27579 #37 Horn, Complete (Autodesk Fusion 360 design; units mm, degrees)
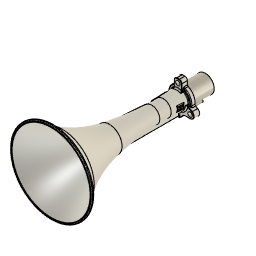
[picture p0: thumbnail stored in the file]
parameter "Bolt_Hole_Tolerance" = 1.5875 (= "( 1 / 16 ) * 1 in")
parameter "Dowel_Hole_Tolerance" = 0.0248 (= "( 1 / 1024 ) * 1 in")
canvas "Canvas1"
sketch "Main Profile" plane through (0, 0, 0) normal (1, 0, 0) x axis (0, 1, 0)
  line L1 (0, -22.225) -> (0, 22.225)
  line L2 (-53.975, 22.225) -> (0, 22.225)
  line L3 (-53.975, 44.45) -> (-53.975, 22.225)
  line L4 (-383.3812, 0) -> (0, 0)
  line L5 (-68.2625, 44.45) -> (-53.975, 44.45)
  line L6 (-53.975, -22.225) -> (0, -22.225)
  line L7 (-53.975, 22.225) -> (-53.975, -22.225)
  line L8 (-53.975, -38.1) -> (-53.975, -22.225)
  line L9 (-68.2625, -38.1) -> (-53.975, -38.1)
  line L10 (-68.2625, 44.45) -> (-68.2625, -38.1)
  line L11 (-133.2594, 16.9307) -> (0, 11.1125)
  line L12 (-63.5, 28.575) -> (-53.975, 28.575)
  line L13 (-63.5, 17.063) -> (-63.5, 28.575)
  line L14 (-133.1209, 20.1027) -> (-63.5, 17.063)
  line L15 (-383.3812, -101.6) -> (-383.3812, 101.6)
  line L16 (-68.2625, 17.2709) -> (-68.2625, 44.45)
  line L17 (9.1828, 34.925) -> (-68.2625, 34.925)
  line L18 (-34.1313, 22.225) -> (-34.1313, -22.225)
  line L19 (-133.2594, -16.9307) -> (0, -11.1125)
  line L20 (-68.2625, -17.2709) -> (-68.2625, -38.1)
  line L21 (-68.2625, -17.2709) -> (-133.1209, -20.1027)
  line L22 (-378.6187, 101.6) -> (-383.3812, 101.6)
  line L23 (-378.6188, 97.4927) -> (-378.6187, 101.6)
  line L24 (-104.775, 20.1844) -> (-63.5, 22.225)
  line L25 (-238.8919, 0) -> (-238.8919, 28.575)
  line L26 (-254.0174, -34.925) -> (-68.2625, -34.925)
  arc A1 centre (-98.1996, 819.9324) radius 803.7667 clockwise from (-133.2594, 16.9307) to (-238.8919, 28.575)
  arc A2 centre (-186.0951, 325.5432) radius 301.625 clockwise from (-238.8919, 28.575) to (-383.3812, 97.3858)
  arc A3 centre (-98.1996, 819.9324) radius 800.5917 clockwise from (-133.1209, 20.1027) to (-238.3362, 31.701)
  arc A4 centre (-186.0951, 325.5432) radius 298.45 clockwise from (-238.3362, 31.701) to (-383.3812, 101.6)
  arc A5 centre (-186.0951, -325.5432) radius 298.45 clockwise from (-383.3812, -101.6) to (-238.3362, -31.701)
  arc A6 centre (-186.0951, -325.5432) radius 301.625 clockwise from (-383.3812, -97.3858) to (-238.8919, -28.575)
  arc A7 centre (-98.1996, -819.9324) radius 800.5917 clockwise from (-238.3362, -31.701) to (-133.1209, -20.1027)
  arc A8 centre (-98.1996, -819.9324) radius 803.7667 clockwise from (-238.8919, -28.575) to (-133.2594, -16.9307)
  arc A9 centre (-119.8256, 324.6126) radius 304.8 clockwise from (-104.775, 20.1844) to (-133.1207, 20.1027)
  point P4 (0, 0)
  point P1 (0, 0)
  point P7 (0, 0)
  point P13 (0, 11.1125)
  point P15 (-53.975, 28.575)
  point P21 (-383.3812, 0)
  point P8 (-383.3812, 0)
  point P22 (-68.2625, 17.2709)
  point P23 (-68.2625, 34.925)
  point P27 (-383.3812, 97.3858)
  point P19 (-383.3812, 101.6)
  point P31 (-383.3812, 101.6)
  point P33 (-34.1313, -22.225)
  point P34 (-34.1313, 22.225)
  point P45 (0, -11.1125)
  point P14 (-133.2594, 16.9307)
  point P44 (-133.2594, -16.9307)
  point P18 (-133.1209, 20.1027)
  point P42 (-133.1209, -20.1027)
  point P25 (-238.8919, 28.575)
  point P40 (-238.8919, -28.575)
  point P39 (-383.3812, -97.3858)
  point P29 (-238.3362, 31.701)
  point P37 (-238.3362, -31.701)
  point P36 (-383.3812, -101.6)
  point P46 (-68.2625, -17.2709)
  point P48 (-378.6188, 97.4927)
  point P49 (-63.5, 22.225)
  point P51 (-104.775, 20.1844)
  point P54 (-238.8919, 0)
  point P50 (-104.775, 20.1844)
  point P52 (-133.1207, 20.1027)
  point P55 (-68.2625, -34.925)
  point P56 (-254.0174, -34.925)
  point P2 (0, 22.225)
  point P5 (-53.975, 22.225)
  point P3 (0, -22.225)
  point P6 (-53.975, 44.45)
  point P9 (-68.2625, 44.45)
  point P16 (-63.5, 28.575)
  point P20 (-383.3812, -101.6)
  point P47 (-378.6187, 101.6)
  point P12 (-68.2625, -38.1)
  vertical L1
  coincident L1 P4
  coincident P1 P4
  midpoint P1 L1
  perpendicular L1 L2
  perpendicular L2 L3
  coincident P1 P7
  perpendicular L1 L4
  perpendicular L3 L5
  perpendicular L1 L6
  vertical L7
  perpendicular L6 L8
  perpendicular L8 L9
  vertical L10
  coincident L1 P13
  coincident L3 P15
  perpendicular L3 L12
  perpendicular L12 L13
  parallel L11 L14
  vertical L15
  midpoint L15 P21
  coincident P8 P21
  coincident L14 P22
  coincident L10 P22
  coincident L10 P23
  perpendicular L16 L17
  tangent L11 A1
  coincident L15 P27
  tangent A1 A2
  tangent L14 A3
  concentric A1 A3
  tangent A3 A4
  concentric A2 A4
  coincident P19 P31
  coincident L6 P33
  coincident L2 P34
  perpendicular L2 L18
  symmetric L4 P13 P45
  symmetric L4 P14 P44
  symmetric L4 P18 P42
  symmetric L4 P25 P40
  symmetric L4 A1 A8
  symmetric L4 P27 P39
  symmetric L4 A2 A6
  symmetric L4 P29 P37
  symmetric L4 A3 A7
  symmetric L4 P31 P36
  symmetric L4 A4 A5
  coincident L10 P46
  perpendicular L9 L20
  tangent A7 L21
  perpendicular L15 L22
  coincident A4 P48
  vertical L23
  coincident L13 P49
  tangent L24 A9
  coincident L24 P51
  coincident L4 P54
  perpendicular L4 L25
  coincident P50 P51
  tangent L14 A9
  coincident A3 P52
  tangent A3 A9
  coincident L10 P55
  perpendicular L20 L26
  coincident A5 P56
  dimension "d1" distance P2 P5 = 53.975 (= "2 1/8")
  dimension "d2" distance P2 P3 = 44.45 (= "1 3/4")
  dimension "d3" distance P6 L4 = 44.45 (= "1 3/4")
  dimension "d4" distance P6 P9 = 14.2875 (= "( 9 / 16 ) * 1 in")
  dimension "d5" distance L4 L9 = 38.1
  dimension "d6" distance P4 P13 = 11.1125 (= "( 7 / 16 ) * 1 in")
  dimension "d7" distance L11 L14 = 3.175 (= "( 1 / 8 ) * 1 in")
  dimension "d9" distance P15 P16 = 9.525 (= "( 3 / 8 ) * 1 in")
  dimension "d10" distance L4 L12 = 28.575
  dimension "d11" distance L4 L17 = 34.925 (= "1 3/8")
  dimension "d12" distance P19 P20 = 203.2
  dimension "d17" distance L1 L18 = 34.1313 (= "1 11/32")
  dimension "d68" distance P19 P47 = 4.7625 (= "( 3 / 16 ) * 1 in")
  dimension "d114" distance P16 P49 = 6.35 (= "( 1 / 4 ) * 1 in")
  dimension "d115" distance L13 P50 = 41.275 (= "1 5/8")
  dimension "d116" radius A9 = 304.8
  dimension "d157" distance L15 L18 = 349.25 (= "13 3/4")
  dimension "d172" angle L4 L11 = 2.5
  dimension "d173" radius A2 = 301.625 (= "11 7/8")
  dimension "d174" distance P25 P54 = 28.575 (= "1 1/8")
  dimension "d175" distance P12 P55 = 3.175 (= "( 1 / 8 ) * 1 in")
revolve "Revolve1" sketch "Main Profile" AlongAngle 360
revolve "Revolve3" sketch "Main Profile" AlongAngle 360
fillet "Fillet16" radius 101.6
sketch "Flange Profile" plane through (0, -53.975, 0) normal (0, 1, 0) x axis (-1, 0, 0)
  line L1 (0, 34.925) -> (0, 0)
  line L2 (0, 44.45) -> (0, 34.925)
  line L3 (3.175, 44.45) -> (-3.175, 44.45)
  line L4 (9.525, 31.1085) -> (9.525, 38.1)
  line L5 (-30.2459, -17.4625) -> (0, 0)
  line L6 (30.2459, -17.4625) -> (0, 0)
  line L7 (30.2459, -26.9875) -> (15.0812, -26.9875)
  line L8 (29.9633, -6.3008) -> (35.0084, -9.2136)
  line L9 (0, -31.75) -> (0, 0)
  line L10 (0, -38.1) -> (0, -31.75)
  line L11 (3.9688, -38.1) -> (-3.9688, -38.1)
  line L12 (15.0812, -26.9875) -> (3.9688, -38.1)
  line L13 (-15.0812, -26.9875) -> (-3.9688, -38.1)
  line L14 (-30.2459, -26.9875) -> (-15.0812, -26.9875)
  line L15 (-29.9633, -6.3008) -> (-35.0084, -9.2136)
  line L16 (-9.525, 31.1085) -> (-9.525, 38.1)
  line L17 (9.525, 20.0805) -> (9.525, 31.1085)
  line L18 (-9.525, 20.0805) -> (-9.525, 31.1085)
  line L19 (22.1527, -1.7913) -> (29.9633, -6.3008)
  line L20 (-22.1527, -1.7913) -> (-29.9633, -6.3008)
  circle C1 centre (0, 0) radius 22.225
  circle C2 centre (0, 0) radius 28.575
  circle C3 centre (0, 34.925) radius 5.5563
  arc A1 centre (3.175, 38.1) radius 6.35 clockwise from (3.175, 44.45) to (9.525, 38.1)
  arc A2 centre (15.875, 31.1085) radius 6.35 clockwise from (12.9886, 25.4524) to (9.525, 31.1085)
  arc A3 centre (0, 0) radius 28.575 clockwise from (12.9886, 25.4524) to (28.3957, -3.196)
  circle C4 centre (-30.2459, -17.4625) radius 5.5563
  circle C5 centre (30.2459, -17.4625) radius 5.5563
  arc A4 centre (30.2459, -17.4625) radius 9.525 clockwise from (35.0084, -9.2136) to (30.2459, -26.9875)
  arc A5 centre (31.5508, -3.5512) radius 3.175 clockwise from (29.9633, -6.3008) to (28.3957, -3.196)
  circle C6 centre (0, -31.75) radius 3.9688
  arc A6 centre (-30.2459, -17.4625) radius 9.525 clockwise from (-30.2459, -26.9875) to (-35.0084, -9.2136)
  arc A7 centre (-31.5508, -3.5512) radius 3.175 clockwise from (-28.3957, -3.196) to (-29.9633, -6.3008)
  arc A8 centre (0, 0) radius 28.575 clockwise from (-28.3957, -3.196) to (-12.9886, 25.4524)
  arc A9 centre (-15.875, 31.1085) radius 6.35 clockwise from (-9.525, 31.1085) to (-12.9886, 25.4524)
  arc A10 centre (-3.175, 38.1) radius 6.35 clockwise from (-9.525, 38.1) to (-3.175, 44.45)
  point P1 (0, 0)
  point P3 (0, 0)
  point P4 (0, 34.925)
  point P5 (0, 34.925)
  point P6 (0, 34.925)
  point P10 (0, 44.45)
  point P7 (0, 44.45)
  point P30 (0, 0)
  point P31 (0, -31.75)
  point P32 (0, -31.75)
  point P33 (0, -31.75)
  point P37 (0, -38.1)
  point P34 (0, -38.1)
  point P9 (3.175, 44.45)
  point P52 (-3.175, 44.45)
  point P11 (9.525, 38.1)
  point P50 (-9.525, 38.1)
  point P13 (9.525, 31.1085)
  point P49 (-9.525, 31.1085)
  point P14 (12.9886, 25.4524)
  point P47 (-12.9886, 25.4524)
  point P16 (28.3957, -3.196)
  point P45 (-28.3957, -3.196)
  point P24 (15.0812, -26.9875)
  point P39 (-15.0812, -26.9875)
  point P25 (30.2459, -26.9875)
  point P40 (-30.2459, -26.9875)
  point P26 (35.0084, -9.2136)
  point P42 (-35.0084, -9.2136)
  point P28 (29.9633, -6.3008)
  point P43 (-29.9633, -6.3008)
  point P36 (3.9688, -38.1)
  point P38 (-3.9688, -38.1)
  point P53 (9.525, 20.0805)
  point P54 (-9.525, 20.0805)
  point P55 (22.1527, -1.7913)
  point P56 (-22.1527, -1.7913)
  point P35 (-3.9688, -38.1)
  point P19 (0, 0)
  coincident P1 P3
  vertical L1
  coincident P4 P5
  coincident P5 P6
  parallel L1 L2
  horizontal L3
  coincident L3 P10
  midpoint L3 P10
  coincident P7 P10
  tangent L3 A1
  vertical L4
  tangent A1 L4
  tangent L4 A2
  tangent A2 A3
  concentric C1 A3
  horizontal L7
  tangent L7 A4
  concentric C5 A4
  tangent A4 L8
  tangent L8 A5
  tangent A3 A5
  coincident P1 P30
  vertical L9
  coincident P31 P32
  coincident P32 P33
  parallel L9 L10
  horizontal L11
  midpoint L11 P37
  coincident P34 P37
  symmetric L1 P9 P52
  symmetric L1 P11 P50
  symmetric L1 A1 A10
  symmetric L1 P13 P49
  symmetric L1 P14 P47
  symmetric L1 A2 A9
  symmetric L1 P16 P45
  symmetric L1 A3 A8
  symmetric L1 P24 P39
  symmetric L1 P25 P40
  symmetric L1 P26 P42
  symmetric L1 A4 A6
  symmetric L1 P28 P43
  symmetric L1 A5 A7
  symmetric L1 P36 P38
  coincident C1 P53
  tangent A2 L17
  tangent A9 L18
  coincident C1 P54
  coincident C1 P55
  tangent A5 L19
  coincident C1 P56
  tangent A7 L20
  dimension "d95" distance P3 P4 = 34.925 (= "1 3/8")
  dimension "d96" diameter C3 = 11.1125 (= "( 3 / 8 ) * 1 in + Bolt_Hole_Tolerance")
  dimension "d97" radius A1 = 6.35 (= "( 1 / 4 ) * 1 in")
  dimension "d98" distance P1 L3 = 44.45 (= "1 3/4")
  dimension "d99" distance P5 L4 = 9.525 (= "( 3 / 8 ) * 1 in")
  dimension "d100" radius A2 = 6.35 (= "( 1 / 4 ) * 1 in")
  dimension "d101" radius A3 = 28.575 (= "1 1/8")
  dimension "d104" radius A4 = 9.525 (= "( 3 / 8 ) * 1 in")
  dimension "d105" angle L7 L8 = 30
  dimension "d106" radius A5 = 3.175 (= "( 1 / 8 ) * 1 in")
  dimension "d107" distance P30 P31 = 31.75 (= "1 1/4")
  dimension "d108" diameter C6 = 7.9375 (= "( 5 / 16 ) * 1 in")
  dimension "d109" distance P35 P36 = 7.9375 (= "( 5 / 16 ) * 1 in")
  dimension "d110" angle L7 L12 = 135
  dimension "d111" distance P19 L11 = 38.1 (= "1 1/2")
  dimension "d103" C-Pattern1-Angle = 360
extrude "Extrude2" add sketch "Flange Profile" profile of C1 C2 C3 L3 A1 L4 C4 C5 L7 A4 L8 C6 L11 L12 L13 L14 A6 L15 L16 A10 L17 L18 L19 L20 against normal blind 14.2875 (magnitude of "( -9 / 16 ) * 1 in")
delete_face "DeleteFace8"
extrude "Extrude6" add sketch "Main Profile" profile of A5 A7 L20 L21 L26 along normal blind 3.175 (= "( 1 / 8 ) * 1 in")
mirror "Mirror5" mirrorStitchTolerance 0.1016
extrude "Extrude8" add of existing geometry blind 1.27
delete_face "DeleteFace11"
delete_face "DeleteFace12"
fillet "Fillet18" radius 3.175 (= "( 1 / 8 ) * 1 in")
fillet "Fillet22" radius 76.2
fillet "Fillet23" radius 1.5875 (= "( 1 / 16 ) * 1 in")
fillet "Fillet19" radius 3.175 (= "( 1 / 8 ) * 1 in")
fillet "Fillet20" radius 1.5875 (= "( 1 / 16 ) * 1 in")
extrude "Extrude4" cut sketch "Flange Profile" profile of C3 C4 C5 against normal blind 14.3002
extrude "Extrude5" cut sketch "Flange Profile" profile of C2 C6 against normal blind 9.525 (magnitude of "( -3 / 8 ) * 1 in")
sketch "Main Profile" plane through (0, -63.5, 0) normal (0, 1, 0) x axis (-1, 0, 0)
  circle C1 centre (0, -31.75) radius 3.9687
  circle C2 centre (0, -31.75) radius 3.175
  concentric C1 C2
  dimension "d137" diameter C2 = 6.35 (= "( 1 / 4 ) * 1 in")
extrude "Extrude1" new body sketch "Main Profile" along normal blind 53.975 (= "2 1/8") bodies "27282 Orifice Pin #4"
offset_faces "OffsetFaces1"
work_plane "WorkPlane1" RotateAngle -180
sketch "Orifice & Number Profile" plane through (0, -43.2509, -35.7188) normal (0, 0, -1) x axis (1, 0, 0)
  line L1 (3.9688, -33.7259) -> (-3.9687, -33.7259)
  line L2 (3.9688, 20.2491) -> (-3.9687, 20.2491)
  line L3 (0, 20.2491) -> (0, -33.7259)
  line L4 (-22.225, -43.2509) -> (22.225, -43.2509)
  line L5 (1.5875, -9.1196) -> (1.5875, -33.7259)
  line L6 (0, -9.1196) -> (1.5875, -9.1196)
  circle C1 centre (0, -9.1196) radius 1.1906
  point P6 (0, -33.7259)
  point P7 (0, 20.2491)
  point P8 (0, -9.1196)
  point P11 (1.5875, -33.7259)
  point P13 (0, -9.1196)
  point P12 (1.5875, -9.1196)
  midpoint L1 P6
  midpoint L2 P7
  coincident L3 P8
  coincident L1 P11
  perpendicular L1 L5
  coincident L3 P13
  perpendicular L3 L6
  coincident P8 P13
  dimension "d143" diameter C1 = 2.3813 (= "( 3 / 32 ) * 1 in")
  dimension "d144" distance P8 L4 = 34.1313
  dimension "d145" distance P12 P13 = 1.5875 (= "( 1 / 16 ) * 1 in")
  dimension "d146" Text1-Height = 3.175 (= "( 1 / 8 ) * 1 in")
emboss "Emboss1" sketch "Orifice & Number Profile" Depth -0.1984 (= "( -1 / 128 ) * 1 in") Horizontal Distance 0 Vertical Distance 0 Rotation Angle 0
extrude "Extrude2" cut sketch "Orifice & Number Profile" profile of C1 against normal blind 3.175 (magnitude of "( -1 / 8 ) * 1 in")
fillet "Fillet21" radius 1.5875 (= "( 1 / 16 ) * 1 in")
fillet "Fillet24" radius 0.7937 (= "( 1 / 32 ) * 1 in")
canvas "Canvas8"
sketch "Branding Profile 1" plane through (0, 0, 0) normal (0, 0, 1) x axis (1, 0, 0)
  line L1 (0, 25.4) -> (0, 0)
  line L2 (-21.8309, -71.2807) -> (-4.4402, -71.2807)
  curve K1 (-4.4402, -71.2807) -> (-4.4156, -104.775)
  line L3 (-20.1844, -104.775) -> (20.1844, -104.775)
  curve K2 (4.4156, -104.775) -> (4.4402, -71.2807)
  line L4 (4.4402, -71.2807) -> (21.8309, -71.2807)
  curve K3 (21.8309, -71.2807) -> (22.1357, -65.0091)
  line L5 (10.3702, -65.0091) -> (22.1504, -65.0091)
  curve K4 (10.3702, -65.0091) -> (10.3604, -71.2807)
  line L6 (-10.3604, -71.2807) -> (10.3604, -71.2807)
  curve K5 (-10.3604, -71.2807) -> (-10.3702, -65.0091)
  line L7 (-22.1504, -65.0091) -> (-10.3702, -65.0091)
  curve K6 (-22.1357, -65.0091) -> (-21.8309, -71.2807)
  curve K7 (-4.4156, -104.775) -> (-4.4142, -133.1209)
  line L8 (-20.1027, -133.1209) -> (20.1027, -133.1209)
  curve K8 (4.4142, -133.1209) -> (4.4156, -104.775)
  line L9 (-20.1844, -104.775) -> (20.1844, -104.775)
  curve K9 (-4.4142, -133.1209) -> (-4.5387, -238.3362)
  line L10 (-31.701, -238.3362) -> (31.701, -238.3362)
  curve K10 (4.5387, -238.3362) -> (4.4142, -133.1209)
  line L11 (-20.1027, -133.1209) -> (20.1027, -133.1209)
  line L12 (-20.1844, -104.775) -> (-21.8309, -71.2807)
  line L13 (-20.0636, -114.261) -> (-21.7878, -76.2)
  line L14 (-18.2795, -114.1801) -> (-20.0636, -114.261)
  line L15 (-20.0037, -76.1192) -> (-18.2795, -114.1801)
  line L16 (-21.7878, -76.2) -> (-20.0037, -76.1192)
  line L17 (-24.6635, -68.2625) -> (-34.6116, -68.2625)
  line L18 (-20.0957, -126.9609) -> (-18.315, -127.0981)
  line L19 (-25.2181, -193.4389) -> (-20.0957, -126.9609)
  line L20 (-23.4374, -193.5761) -> (-25.2181, -193.4389)
  line L21 (-18.315, -127.0981) -> (-23.4374, -193.5761)
  line L22 (20.1844, -104.775) -> (21.8309, -71.2807)
  line L23 (20.004, -76.1123) -> (21.7878, -76.2)
  line L24 (19.3804, -88.797) -> (20.004, -76.1123)
  line L25 (21.1642, -88.8847) -> (19.3804, -88.797)
  line L26 (21.7878, -76.2) -> (21.1642, -88.8847)
  line L27 (34.6116, -68.2625) -> (24.6635, -68.2625)
  arc A1 centre (-326.4745, -119.8309) radius 306.6599 clockwise from (-20.1844, -104.775) to (-20.1027, -133.1209)
  arc A2 centre (-816.554, -98.572) radius 797.2003 clockwise from (-20.1027, -133.1209) to (-31.701, -238.3362)
  arc A3 centre (816.554, -98.572) radius 797.2003 clockwise from (31.701, -238.3362) to (20.1027, -133.1209)
  arc A4 centre (326.4745, -119.8309) radius 306.6599 clockwise from (20.1027, -133.1209) to (20.1844, -104.775)
  point P1 (0, 0)
  point P2 (0, 0)
  point P5 (-21.8309, -71.2807)
  point P36 (-21.8309, -71.2807)
  point P27 (-20.1844, -104.775)
  point P37 (-20.1844, -104.775)
  point P39 (-20.1844, -104.775)
  point P35 (-20.1027, -133.1209)
  point P38 (-20.1027, -133.1209)
  point P31 (-31.701, -238.3362)
  point P42 (-31.701, -238.3362)
  point P23 (-20.1027, -133.1209)
  point P41 (-20.1027, -133.1209)
  point P48 (-19.8653, -114.252)
  point P49 (-21.5895, -76.191)
  point P56 (-25.0203, -193.4541)
  point P57 (-19.8978, -126.9762)
  point P64 (21.8309, -71.2807)
  point P65 (20.1844, -104.775)
  point P62 (20.1027, -133.1209)
  point P63 (20.1844, -104.775)
  point P60 (20.1027, -133.1209)
  point P59 (31.701, -238.3362)
  point P44 (-21.7878, -76.2)
  point P45 (-20.0636, -114.261)
  point P47 (-20.0037, -76.1192)
  point P53 (-20.0957, -126.9609)
  point P54 (-25.2181, -193.4389)
  point P52 (-18.315, -127.0981)
  point P66 (21.7878, -76.2)
  point P69 (21.1642, -88.8847)
  coincident P1 P2
  vertical L1
  coincident P5 P36
  coincident P27 P37
  coincident P27 P39
  coincident P35 P38
  tangent L12 A1
  coincident P31 P42
  coincident P23 P41
  tangent A1 A2
  perpendicular L13 L14
  perpendicular L14 L15
  perpendicular L15 L16
  coincident L14 P48
  coincident A1 P48
  coincident L16 P49
  coincident L12 P49
  perpendicular L18 L19
  perpendicular L19 L20
  perpendicular L20 L21
  coincident L20 P56
  coincident A2 P56
  coincident A1 P57
  coincident L18 P57
  symmetric L1 P36 P64
  symmetric L1 P37 P65
  symmetric L1 P38 P62
  symmetric L1 P39 P63
  symmetric L1 A1 A4
  symmetric L1 P41 P60
  symmetric L1 P42 P59
  symmetric L1 A2 A3
  perpendicular L22 L23
  perpendicular L23 L24
  perpendicular L24 L25
  perpendicular L25 L26
  dimension "d190" distance P44 P49 = 0.1984 (= "( 1 / 128 ) * 1 in")
  dimension "d191" distance P45 P48 = 0.1984 (= "d190")
  dimension "d192" distance P44 P45 = 38.1 (= "1 1/2")
  dimension "d193" distance P44 L17 = 7.9375 (= "( 5 / 16 ) * 1 in")
  dimension "d194" distance P47 P49 = 1.5875 (= "( 1 / 16 ) * 1 in")
  dimension "d195" distance P53 P57 = 0.1984 (= "( 1 / 128 ) * 1 in")
  dimension "d196" distance P54 P56 = 0.1984 (= "d195")
  dimension "d197" distance P52 P57 = 1.5875 (= "( 1 / 16 ) * 1 in")
  dimension "d198" distance P45 P53 = 12.7 (= "( 1 / 2 ) * 1 in")
  dimension "d199" distance P53 P54 = 66.675 (= "2 5/8")
  dimension "d202" distance L22 L26 = 0.1984 (= "( 1 / 128 ) * 1 in")
  dimension "d203" distance L22 L24 = 1.5875 (= "( 1 / 16 ) * 1 in")
  dimension "d204" distance P66 L27 = 7.9375 (= "d193")
  dimension "d205" distance P66 P69 = 12.7 (= "( 1 / 2 ) * 1 in")
extrude "Extrude9" add sketch "Branding Profile 1" profile of L3 L8 L9 L11 L12 A1 A2 L13 L14 L15 L16 L18 L19 L20 L21 distance 19.05 (= "( 3 / 4 ) * 1 in")
delete_face "DeleteFace13"
extrude "Extrude10" add sketch "Branding Profile 1" profile of L22 L23 L24 L25 L26 distance 9.525 (= "( 3 / 8 ) * 1 in")
fillet "Fillet25" radius 6.35 (= "( 1 / 4 ) * 1 in")
fillet "Fillet26" radius 3.175 (= "( 1 / 8 ) * 1 in")
fillet "Fillet27" radius 0.7937 (= "( 1 / 32 ) * 1 in")
sketch "Branding Profile 2" plane through (-25.188, -1.141, 0) normal (-0.999, -0.0453, 0) x axis (0.0453, -0.999, 0)
  curve K1 (75.1359, -8.7898) -> (75.9363, -9.525)
  line L1 (104.0174, -9.525) -> (75.9363, -9.525)
  line L2 (112.415, -9.525) -> (104.0174, -9.525)
  curve K2 (112.415, -9.525) -> (113.2359, -8.7717)
  line L3 (113.2359, 8.7717) -> (113.2359, -8.7717)
  curve K3 (113.2359, 8.7717) -> (112.415, 9.525)
  line L4 (104.0174, 9.525) -> (112.415, 9.525)
  line L5 (75.9363, 9.525) -> (104.0174, 9.525)
  curve K4 (75.9363, 9.525) -> (75.1359, 8.7898)
  line L6 (75.1359, -8.7898) -> (75.1359, 8.7898)
  line L7 (86.4846, -4.4596) -> (86.4846, -1.4472)
  line L8 (87.3217, -5.0926) -> (88.9649, -4.6273)
  line L9 (84.9781, -6.3626) -> (84.9781, 6.0597)
  line L10 (83.6022, -6.7697) -> (83.6022, -7.1367)
  line L11 (80.6784, 8.1969) -> (80.0581, 8.6312)
  line L12 (87.3127, 0.5429) -> (86.9681, 0.5429)
  line L13 (81.646, -6.7702) -> (82.7145, -6.2258)
  line L14 (107.7255, -0.9686) -> (108.253, -0.9686)
  line L15 (107.3489, 0.9145) -> (107.3489, -1.3453)
  line L16 (109.3111, 9.0165) -> (106.1747, 7.6922)
  line L17 (107.3489, 0.9145) -> (107.3489, 6.3029)
  line L18 (97.7378, 5.487) -> (96.9845, 5.487)
  line L19 (109.8343, 7.8519) -> (109.8343, 8.6696)
  line L20 (108.253, 0.5379) -> (107.7255, 0.5379)
  line L21 (96.6079, -4.8397) -> (96.6079, 5.1103)
  line L22 (107.579, 6.6498) -> (109.6042, 7.5049)
  line L23 (109.7082, -7.2726) -> (107.5684, -6.2903)
  line L24 (105.7144, -6.6138) -> (105.7144, 6.9982)
  line L25 (106.1534, -7.2984) -> (109.3939, -8.7861)
  line L26 (108.6297, -0.592) -> (108.6297, 0.1613)
  line L27 (89.3551, 4.8553) -> (89.3551, 5.2322)
  line L28 (87.3543, 4.6563) -> (88.6893, 4.3319)
  line L29 (86.4846, 1.0264) -> (86.4846, 3.9726)
  line L30 (89.2038, -6.0315) -> (85.8108, -6.9922)
  line L31 (80.8803, -6.301) -> (80.8803, 7.809)
  line L32 (83.2091, -7.7782) -> (80.495, -9.1611)
  line L33 (88.9427, 5.7567) -> (85.6196, 6.5641)
  line L34 (103.9994, 6.3232) -> (103.9994, -6.3604)
  line L35 (109.9277, -8.4438) -> (109.9277, -7.6149)
  line L36 (107.3489, -5.948) -> (107.3489, -1.3453)
  line L37 (87.7962, -0.4801) -> (87.7962, 0.0594)
  line L38 (89.5846, -5.0959) -> (89.5846, -5.528)
  line L39 (86.9681, -0.9636) -> (87.3127, -0.9636)
  line L40 (79.2458, -8.3956) -> (79.2458, 8.2084)
  line L41 (86.4846, 1.0264) -> (86.4846, -1.4472)
  line L42 (90.8706, 2.3877) -> (90.8706, 4.8031)
  line L43 (91.1532, -2.0448) -> (91.1532, -5.0326)
  line L44 (91.5205, -1.6682) -> (91.5298, -1.6682)
  line L45 (94.393, 5.2738) -> (91.3413, 5.2738)
  line L46 (95.1369, -5.0326) -> (95.1369, -1.5281)
  line L47 (91.5298, -5.4092) -> (94.7603, -5.4092)
  line L48 (93.2463, -4.6653) -> (92.2812, -4.6653)
  line L49 (94.8468, -0.6393) -> (92.2593, 2.9021)
  line L50 (92.5598, 4.1584) -> (93.1259, 4.1584)
  line L51 (92.1758, 3.5592) -> (92.1758, 3.7743)
  line L52 (91.8971, -4.2813) -> (91.8971, -2.0448)
  line L53 (93.3403, -1.131) -> (90.9524, 2.1371)
  line L54 (92.1758, 3.158) -> (92.1758, 3.5592)
  line L55 (93.505, 3.8359) -> (93.5982, 3.2617)
  line L56 (103.5001, -6.7165) -> (102.7468, -6.4572)
  line L57 (98.4442, -4.2166) -> (100.7366, -4.5044)
  line L58 (100.6427, -6.011) -> (97.2673, -5.5871)
  line L59 (93.6304, -4.2813) -> (93.6304, -2.0198)
  line L60 (98.1144, -3.8429) -> (98.1144, 5.1103)
  line L61 (94.7876, 3.3576) -> (94.7876, 4.8791)
  line L62 (101.0663, -4.8781) -> (101.0663, -5.6373)
  line L63 (102.7468, 6.42) -> (103.5001, 6.6793)
  line L64 (102.4928, -6.1011) -> (102.4928, 6.0639)
  arc A1 centre (85.4971, 6.0597) radius 0.519 clockwise from (84.9781, 6.0597) to (85.6196, 6.5641)
  arc A2 centre (103.6227, 6.3232) radius 0.3766 clockwise from (103.5001, 6.6793) to (103.9994, 6.3232)
  arc A3 centre (87.1425, -4.4596) radius 0.6578 clockwise from (87.3217, -5.0926) to (86.4846, -4.4596)
  arc A4 centre (80.4068, 7.809) radius 0.4736 clockwise from (80.6784, 8.1969) to (80.8803, 7.809)
  arc A5 centre (87.3127, 0.0594) radius 0.4835 clockwise from (87.3127, 0.5429) to (87.7962, 0.0594)
  arc A6 centre (109.5511, -7.6149) radius 0.3766 clockwise from (109.7082, -7.2726) to (109.9277, -7.6149)
  arc A7 centre (106.4677, -6.6138) radius 0.7533 clockwise from (106.1534, -7.2984) to (105.7144, -6.6138)
  arc A8 centre (109.5511, -8.4438) radius 0.3766 clockwise from (109.9277, -8.4438) to (109.3939, -8.7861)
  arc A9 centre (109.4576, 7.8519) radius 0.3766 clockwise from (109.8343, 7.8519) to (109.6042, 7.5049)
  arc A10 centre (106.4677, 6.9982) radius 0.7533 clockwise from (105.7144, 6.9982) to (106.1747, 7.6922)
  arc A11 centre (107.7255, 6.3029) radius 0.3766 clockwise from (107.3489, 6.3029) to (107.579, 6.6498)
  arc A12 centre (108.253, -0.592) radius 0.3766 clockwise from (108.6297, -0.592) to (108.253, -0.9686)
  arc A13 centre (108.253, 0.1613) radius 0.3766 clockwise from (108.253, 0.5379) to (108.6297, 0.1613)
  arc A14 centre (107.7255, -5.948) radius 0.3766 clockwise from (107.5684, -6.2903) to (107.3489, -5.948)
  arc A15 centre (109.4576, 8.6696) radius 0.3766 clockwise from (109.3111, 9.0165) to (109.8343, 8.6696)
  arc A16 centre (107.7255, 0.9145) radius 0.3766 clockwise from (107.7255, 0.5379) to (107.3489, 0.9145)
  arc A17 centre (82.8823, -7.1367) radius 0.7199 clockwise from (83.6022, -7.1367) to (83.2091, -7.7782)
  arc A18 centre (88.8165, 4.8553) radius 0.5386 clockwise from (89.3551, 4.8553) to (88.6893, 4.3319)
  arc A19 centre (85.6325, -6.3626) radius 0.6544 clockwise from (85.8108, -6.9922) to (84.9781, -6.3626)
  arc A20 centre (87.1882, 3.9726) radius 0.7035 clockwise from (86.4846, 3.9726) to (87.3543, 4.6563)
  arc A21 centre (79.762, 8.2084) radius 0.5162 clockwise from (79.2458, 8.2084) to (80.0581, 8.6312)
  arc A22 centre (89.0612, -5.528) radius 0.5233 clockwise from (89.5846, -5.528) to (89.2038, -6.0315)
  arc A23 centre (89.0976, -5.0959) radius 0.487 clockwise from (88.9649, -4.6273) to (89.5846, -5.0959)
  arc A24 centre (87.3127, -0.4801) radius 0.4835 clockwise from (87.7962, -0.4801) to (87.3127, -0.9636)
  arc A25 centre (81.4069, -6.301) radius 0.5266 clockwise from (81.646, -6.7702) to (80.8803, -6.301)
  arc A26 centre (86.9681, 1.0264) radius 0.4835 clockwise from (86.9681, 0.5429) to (86.4846, 1.0264)
  arc A27 centre (107.7255, -1.3453) radius 0.3766 clockwise from (107.3489, -1.3453) to (107.7255, -0.9686)
  arc A28 centre (88.8153, 5.2322) radius 0.5398 clockwise from (88.9427, 5.7567) to (89.3551, 5.2322)
  arc A29 centre (82.9917, -6.7697) radius 0.6105 clockwise from (82.7145, -6.2258) to (83.6022, -6.7697)
  arc A30 centre (80.105, -8.3956) radius 0.8592 clockwise from (80.495, -9.1611) to (79.2458, -8.3956)
  arc A31 centre (86.9681, -1.4472) radius 0.4835 clockwise from (86.4846, -1.4472) to (86.9681, -0.9636)
  arc A32 centre (94.393, 4.8791) radius 0.3947 clockwise from (94.393, 5.2738) to (94.7876, 4.8791)
  arc A33 centre (91.5298, -5.0326) radius 0.3766 clockwise from (91.5298, -5.4092) to (91.1532, -5.0326)
  arc A34 centre (91.5298, -2.0448) radius 0.3766 clockwise from (91.1532, -2.0448) to (91.5298, -1.6682)
  arc A35 centre (93.1259, 3.7743) radius 0.3841 clockwise from (93.1259, 4.1584) to (93.505, 3.8359)
  arc A36 centre (93.2463, -4.2813) radius 0.3841 clockwise from (93.6304, -4.2813) to (93.2463, -4.6653)
  arc A37 centre (92.6096, 3.158) radius 0.4338 clockwise from (92.2593, 2.9021) to (92.1758, 3.158)
  arc A38 centre (91.3413, 4.8031) radius 0.4706 clockwise from (90.8706, 4.8031) to (91.3413, 5.2738)
  arc A39 centre (92.5598, 3.7743) radius 0.3841 clockwise from (92.1758, 3.7743) to (92.5598, 4.1584)
  arc A40 centre (91.5205, -2.0448) radius 0.3766 clockwise from (91.5205, -1.6682) to (91.8971, -2.0448)
  arc A41 centre (94.1891, 3.3576) radius 0.5986 clockwise from (94.7876, 3.3576) to (93.5982, 3.2617)
  arc A42 centre (93.6304, -1.5281) radius 1.5065 clockwise from (94.8468, -0.6393) to (95.1369, -1.5281)
  arc A43 centre (91.2954, 2.3877) radius 0.4248 clockwise from (90.9524, 2.1371) to (90.8706, 2.3877)
  arc A44 centre (94.7603, -5.0326) radius 0.3766 clockwise from (95.1369, -5.0326) to (94.7603, -5.4092)
  arc A45 centre (92.2812, -4.2813) radius 0.3841 clockwise from (92.2812, -4.6653) to (91.8971, -4.2813)
  arc A46 centre (92.1238, -2.0198) radius 1.5065 clockwise from (93.3403, -1.131) to (93.6304, -2.0198)
  arc A47 centre (102.8695, 6.0639) radius 0.3766 clockwise from (102.4928, 6.0639) to (102.7468, 6.42)
  arc A48 centre (96.9845, 5.1103) radius 0.3766 clockwise from (96.6079, 5.1103) to (96.9845, 5.487)
  arc A49 centre (100.6897, -5.6373) radius 0.3766 clockwise from (101.0663, -5.6373) to (100.6427, -6.011)
  arc A50 centre (97.3612, -4.8397) radius 0.7533 clockwise from (97.2673, -5.5871) to (96.6079, -4.8397)
  arc A51 centre (100.6897, -4.8781) radius 0.3766 clockwise from (100.7366, -4.5044) to (101.0663, -4.8781)
  arc A52 centre (103.6227, -6.3604) radius 0.3766 clockwise from (103.9994, -6.3604) to (103.5001, -6.7165)
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  point P151 (80.8803, -6.301)
  point P158 (80.8803, -6.301)
  point P93 (98.1144, -3.8429)
  point P94 (98.1144, -3.8429)
  point P100 (108.6297, -0.2154)
  point P123 (105.7144, -6.6138)
  point P155 (105.7144, -6.6138)
  tangent A21 L40
  tangent L11 A21
  tangent L11 A4
  tangent A4 L31
  vertical L31
  tangent L40 A30
  tangent L32 A30
  tangent A17 L32
  vertical L10
  tangent L10 A17
  tangent L10 A29
  tangent L13 A29
  parallel L13 L32
  tangent L13 A25
  coincident P151 P158
  tangent L31 A25
  vertical L9
  tangent A1 L9
  tangent A1 L33
  tangent L33 A28
  tangent L27 A28
  vertical L27
  tangent L27 A18
  tangent A18 L28
  parallel L28 L33
  tangent L28 A20
  vertical L29
  tangent L29 A20
  tangent L29 A26
  tangent L12 A26
  horizontal L12
  tangent A5 L12
  tangent A5 L37
  vertical L37
  tangent A24 L37
  horizontal L39
  tangent A24 L39
  tangent L39 A31
  vertical L7
  tangent L7 A31
  vertical L41
  tangent L9 A19
  tangent A19 L30
  tangent L30 A22
  vertical L38
  tangent A22 L38
  tangent A23 L38
  tangent L8 A23
  tangent L8 A3
  tangent L7 A3
  parallel L8 L30
  horizontal L45
  tangent A32 L45
  vertical L61
  tangent A32 L61
  tangent A41 L61
  tangent A41 L55
  tangent A35 L55
  tangent A35 L50
  horizontal L50
  tangent A39 L50
  vertical L51
  tangent A39 L51
  tangent A38 L45
  vertical L42
  tangent L42 A38
  tangent L42 A43
  tangent A43 L53
  parallel L51 L54
  tangent A37 L54
  tangent A37 L49
  parallel L49 L53
  tangent L49 A42
  vertical L46
  tangent L46 A42
  tangent L53 A46
  tangent A46 L59
  vertical L59
  tangent L46 A44
  horizontal L47
  tangent L47 A44
  tangent A33 L47
  vertical L43
  tangent L43 A33
  tangent L43 A34
  horizontal L44
  tangent L44 A34
  tangent L44 A40
  vertical L52
  tangent A40 L52
  tangent L52 A45
  tangent A36 L59
  tangent L48 A45
  tangent A36 L48
  vertical L21
  tangent L21 A48
  horizontal L18
  tangent L18 A48
  vertical L60
  tangent L21 A50
  tangent A50 L58
  tangent A49 L58
  vertical L62
  tangent A49 L62
  tangent L62 A51
  tangent L57 A51
  parallel L57 L58
  coincident P93 P94
  vertical L64
  tangent L56 A52
  vertical L34
  tangent L34 A52
  tangent A2 L34
  tangent A2 L63
  tangent A47 L63
  tangent A47 L64
  tangent A10 L24
  tangent L16 A10
  tangent L16 A15
  tangent L19 A15
  vertical L19
  tangent A9 L19
  tangent A9 L22
  parallel L16 L22
  tangent A11 L22
  vertical L17
  tangent L17 A11
  tangent L17 A16
  horizontal L20
  tangent L20 A16
  tangent L20 A13
  vertical L26
  tangent A13 L26
  tangent A12 L26
  horizontal L14
  tangent L14 A12
  tangent L14 A27
  vertical L36
  tangent L36 A27
  vertical L15
  midpoint P100 L26
  tangent A14 L36
  tangent A14 L23
  tangent A6 L23
  vertical L35
  tangent A6 L35
  tangent A8 L35
  tangent A8 L25
  parallel L23 L25
  tangent A7 L25
  coincident P123 P155
  tangent A7 L24
  dimension "d357" angle L11 L40 = 55
  dimension "d359" angle L32 L40 = 63
  dimension "d367" angle L55 L61 = 9.219
  dimension "d371" radius A43 = 0.4248
  dimension "d384" distance L45 L50 = 1.1154
  dimension "d395" angle L56 L64 = 109
  dimension "d400" angle L63 L64 = 109
  dimension "d339" angle L23 L35 = 114.659
extrude "Extrude11" add sketch "Branding Profile 2" along normal blind 0.3969 (= "( 1 / 64 ) * 1 in") taper -30
sketch "Branding Profile 3" plane through (-10.252, 0.79, 0) normal (-0.997, 0.0768, 0) x axis (-0.0768, -0.997, 0)
  curve K1 (194.0282, -9.525) -> (194.8046, -8.8343)
  line L1 (194.8046, 8.8343) -> (194.8046, -8.8343)
  curve K2 (194.8046, 8.8343) -> (194.0282, 9.525)
  line L2 (134.0781, 9.525) -> (194.0282, 9.525)
  line L3 (128.9577, 9.525) -> (134.0781, 9.525)
  curve K3 (128.9577, 9.525) -> (128.1296, 8.7746)
  line L4 (128.1296, -8.7746) -> (128.1296, 8.7746)
  curve K4 (128.1296, -8.7746) -> (128.9577, -9.525)
  line L5 (134.0781, -9.525) -> (128.9577, -9.525)
  line L6 (194.0282, -9.525) -> (134.0781, -9.525)
  line L7 (194.8046, 0) -> (128.1296, 0)
  line L8 (194.8046, -3.175) -> (128.1296, -3.175)
  line L9 (161.4671, -4.7625) -> (129.3565, -4.7625)
  line L10 (161.4671, -5.9531) -> (161.4671, -4.7625)
  line L11 (129.3565, -5.9531) -> (161.4671, -5.9531)
  line L12 (129.3565, -4.7625) -> (129.3565, -5.9531)
  line L13 (129.3565, 0) -> (129.3565, -4.7625)
  line L14 (161.4671, 0) -> (161.4671, -4.7625)
  point P12 (128.1296, 0)
  point P13 (194.8046, 0)
  point P14 (128.1296, -3.175)
  point P15 (194.8046, -3.175)
  point P20 (129.3565, 0)
  point P21 (161.4671, 0)
  point P16 (129.3565, -4.7625)
  point P19 (129.3565, -5.9531)
  midpoint L4 P12
  midpoint L1 P13
  coincident L4 P14
  coincident L1 P15
  perpendicular L1 L8
  horizontal L9
  vertical L10
  horizontal L11
  vertical L12
  coincident L7 P20
  perpendicular L7 L13
  perpendicular L7 L14
  midpoint L7 P21
  dimension "d224" distance L7 L8 = 3.175 (= "( 1 / 8 ) * 1 in")
  dimension "d226" distance L8 L9 = 1.5875 (= "( 1 / 16 ) * 1 in")
  dimension "d227" distance P16 P19 = 1.1906 (= "( 3 / 64 ) * 1 in")
  dimension "d225" Text1-Height = 9.525
extrude "Extrude12" add sketch "Branding Profile 3" profile of L9 L10 L11 L12 along normal blind 0.3969 (= "( 1 / 64 ) * 1 in") taper -25
sketch "Branding Profile 4" plane through (25.4721, -1.2522, 0) normal (0.9988, -0.0491, 0) x axis (0.0491, 0.9988, 0)
  curve K1 (-75.5941, -4.7625) -> (-75.0383, -4.2995)
  line L1 (-75.0383, 4.2995) -> (-75.0383, -4.2995)
  curve K2 (-75.0383, 4.2995) -> (-75.5941, 4.7625)
  line L2 (-87.1742, 4.7625) -> (-75.5941, 4.7625)
  curve K3 (-87.1742, 4.7625) -> (-87.7383, 4.2931)
  line L3 (-87.7383, -4.2931) -> (-87.7383, 4.2931)
  curve K4 (-87.7383, -4.2931) -> (-87.1742, -4.7625)
  line L4 (-75.5941, -4.7625) -> (-87.1742, -4.7625)
  line L5 (-75.0383, 0) -> (-87.7383, 0)
  line L6 (-87.7383, -3.175) -> (-75.0383, -3.175)
  point P10 (-87.7383, 0)
  point P11 (-75.0383, 0)
  point P12 (-75.0383, -3.175)
  point P13 (-87.7383, -3.175)
  midpoint L3 P10
  midpoint L1 P11
  coincident L1 P12
  coincident L3 P13
  perpendicular L3 L6
  dimension "d230" distance L5 L6 = 3.175 (= "( 1 / 8 ) * 1 in")
  dimension "d231" Text1-Height = 9.525
extrude "Extrude13" add sketch "Branding Profile 4" along normal blind 0.3969 (= "( 1 / 64 ) * 1 in") taper -21
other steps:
create_component "CreateComponent1"
create_component "CreateComponent2"
named bodies: "27492 #37 Horn", "27282 Orifice Pin #4"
